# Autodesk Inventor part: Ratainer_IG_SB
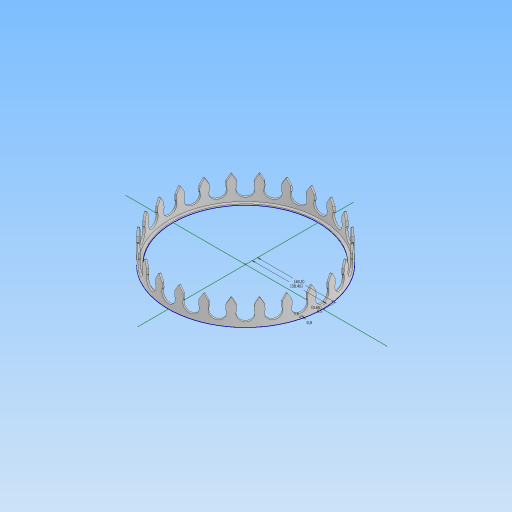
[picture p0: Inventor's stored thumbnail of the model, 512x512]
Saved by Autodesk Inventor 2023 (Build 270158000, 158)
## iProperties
Created: 2024-05
Part Number: Ratainer_IG_SB
Material: 一般
Document SubType Name: Modeling
Designer: kumagai
Density: 1 g/cm^3
Appearance: 既定
Author: kumagai
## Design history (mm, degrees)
derived "CoreSketch.ipt"
  sketch "スケッチ2"
    geometry: L1 (0, 65.337)-(0, -65.337) reference; L2 (-46.2, 0)-(46.2, 0) reference; L3 (-11, 2)-(11, 2) reference; L4 (11, 2)-(11, -2) reference; L5 (11, -2)-(-11, -2) reference; L6 (-11, -2)-(-11, 2) reference; L7 (11, 2)-(33, 2) reference; L8 (33, 2)-(33, -2) reference; L9 (33, -2)-(11, -2) reference; L10 (11, -2)-(11, 2) reference; L11 (22, 2.772)-(22, -2.683) reference; L12 (-33, 2)-(-11, 2) reference; L13 (-11, 2)-(-11, -2) reference; L14 (-11, -2)-(-33, -2) reference; L15 (-33, -2)-(-33, 2) reference; L16 (-22, 4.087)-(-22, -4.199) reference; L17 (-33, 10)-(-11, 10) reference; L18 (-11, 10)-(-11, 6) reference; L19 (-11, 6)-(-33, 6) reference; L20 (-33, 6)-(-33, 10) reference; L21 (-27.353, 10)-(-16.647, 10) reference; L22 (-16.647, 10)-(-16.647, 16) reference; L23 (-16.647, 16)-(-27.353, 16) reference; L24 (-27.353, 16)-(-27.353, 10) reference; L25 (11, 16)-(33, 16) reference; L26 (33, 16)-(33, 12) reference; L27 (33, 12)-(11, 12) reference; L28 (11, 12)-(11, 16) reference; L29 (16.134, 12)-(27.866, 12) reference; L30 (27.866, 12)-(27.866, 6) reference; L31 (27.866, 6)-(16.134, 6) reference; L32 (16.134, 6)-(16.134, 12) reference; L33 (-22, 18.272)-(-22, 9.031) reference; L34 (22, 22.635)-(22, 12.71) reference; L35 (33, -2)-(35, -2) reference; L36 (35, -2)-(35, 10) reference; L37 (35, 10)-(33, 10) reference; L38 (33, 10)-(33, -2) reference; L39 (0, -4)-(37.5, -4) reference; L40 (40.5, -1)-(40.5, 14) reference; L41 (43.9, -8)-(0, -8) reference; L42 (0, -4)-(0, -8) reference; L43 (35, -2)-(39, -2) reference; L44 (39, -2)-(39, 3.066) reference; L45 (38.45, 8.685)-(41.471, 10.429) reference; L46 (38.45, 10)-(35, 10) reference; L47 (40.5, 9.291)-(41.55, 8.685) reference; L48 (41.55, 3.315)-(40.5, 2.709) reference; L49 (37.5, -4)-(40.5, -1) reference; L50 (-43, 43.294)-(-1, 43.294) reference; L51 (-1, 43.294)-(-1, 26) reference; L52 (-1, 26)-(-43, 26) reference; L53 (-43, 26)-(-43, 43.294) reference; L54 (1, 43.294)-(43, 43.294) reference; L55 (43, 43.294)-(43, 26) reference; L56 (43, 26)-(1, 26) reference; L57 (1, 26)-(1, 43.294) reference; L58 (-22, 45.556)-(-22, 31.232) reference; L59 (22, 47.214)-(22, 32.287) reference; L60 (47.5, 4.402)-(47.5, -2.116) reference; L61 (43.6, -11)-(54, -11) reference; L62 (54, -11)-(54, 18) reference; L63 (45.45, -3.315)-(46.5, -2.709) reference; L64 (47.5, -2.116)-(49.192, -3.808) reference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; A1 r 3.1 centre (40, 6) between (39, 3.066) and (38.45, 8.685) reference; A2 r 3.1 centre (47, -6) between (45.45, -3.315) and (49.192, -3.808) reference; A3 r 3.1 centre (47, 13) between (43.9, 13) and (49, 10.631) reference; 2 further points; 1 other entity
    constraints: 1 other
sketch "スケッチ3" dims "d3" = 0.9
  geometry: L1 (0, -56)-(0, 56) reference; C1 r 37.6 at (0, 0); 13 further points
  constraints: 3 coincident, 2 horizontal alignment, 1 centre point, 7 other
  dimensions: "d1" = 38.45 distance from line of point (-38.45, 0) L1 (derived); "d2" = 40.5 distance from line of point (-40.5, 0) L1 (derived); "d4" = 0.5 distance of point (-40.5, 0) point (-40, 0); "d5" = 0.65 distance of point (-38.45, 0) point (-39.1, 0) (derived); "d10" = 1.5 dimension on C1
extrude "押し出し1" new body sketch "スケッチ3" distance "d6" = 13; taper "d7" = 0 deg
sketch "スケッチ4"
  geometry: L1 (13, -40)-(13, 40) reference; L2 (0, -40)-(0, 40) reference; L3 (0, 56)-(0, -56) reference; L4 (-24.112, 0)-(59.102, 0) reference; L5 (10, 3.3)-(10, -3.3); L6 (10, -3.3)-(7.518, -3.208); L7 (7.518, 3.208)-(10, 3.3); L8 (10, 3.3)-(13, 5); L9 (13, -5)-(13, 5); L10 (13, -5)-(10, -3.3); A1 r 3.5 centre (6, 0) between (7.313, 3.245) and (7.313, -3.245); A2 r 0.5 centre (7.5, 3.708) between (7.313, 3.245) and (7.518, 3.208); A3 r 0.5 centre (7.5, -3.708) between (7.518, -3.208) and (7.313, -3.245); 3 further points
  constraints: 12 end point, 6 point on circle, 4 tangent, 3 centre point, 3 point on line, 2 symmetric about line, 1 equal radius, 1 vertical alignment
  dimensions: "d9" = 6 distance from line of A1.centre L2; "d13" = 0.5 radius of A2; "d19" = 3.5 radius of A1; "d21" = 10 distance between parallel lines of L2 L5; "d22" = 3.3 distance from line of L5.end L4; "d23" = 4 distance from line of A1.centre L5 (derived); "d24" = 1.5 horizontal distance of A3.centre A1.centre; "d25" = 7.4162 distance of A3.centre A2.centre (derived); "d26" = 6.4162 dimension on A3 A2 (derived); "d27" = 10 distance of L9.start L8.end
extrude "押し出し2" join sketch "スケッチ3" distance "d11" = 0.6; taper "d12" = 0 deg
extrude "押し出し3" cut sketch "スケッチ4" extent not by distance; stored distance "d14" = 0; taper "d15" = 0 deg
pattern_circular "円形状パターン1" dims angle "d17" = 180 deg
node "ソリッド1"
